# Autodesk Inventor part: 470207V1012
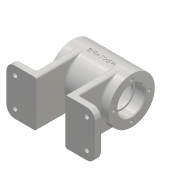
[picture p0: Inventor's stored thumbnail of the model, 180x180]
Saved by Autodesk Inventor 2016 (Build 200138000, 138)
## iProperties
Created: 2017-02
Part Number: 470207V1012
Material: 알루미늄 6061
Document SubType Name: Modeling
Designer: H
Density: 2.7 g/cm^3
Appearance: 알루미늄 - 평지
Mass: 354.768 g
Surface Area: 422.772 cm^2
Volume: 131.396 cm^3
Author: H
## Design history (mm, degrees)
sketch "스케치1"
  geometry: L1 (-35, 27)-(35, 27); L2 (35, 27)-(35, 0); L3 (35, 0)-(-35, 0); L4 (-35, 0)-(-35, 27); L5 (-70.456, 0)-(124.766, 0); 1 further point
  constraints: 10 end point, 2 horizontal, 2 parallel, 1 collinear, 1 perpendicular, 1 point on line
  dimensions: "d0" = 70 distance of L1.start L1.end; "d1" = 35 distance from line of L4 point (0, 0); "d2" = 27 distance of L1.end L2.end
revolve "회전1" sketch "스케치1" stored, may be unused: angle "d3" = 90 deg
sketch "스케치2"
  geometry: L1 (17, -52)-(52, -52); L2 (52, -52)-(52, -60); L3 (52, -60)-(17, -60); L4 (17, -60)-(17, -52); 1 further point
  constraints: 8 end point, 2 parallel, 1 horizontal, 1 perpendicular
  dimensions: "d4" = 35 distance of L2.end L3.end; "d5" = 8 distance of L1.end L2.end; "d6" = 17 distance from line of point (0, 0) L4; "d7" = 60 distance from line of L3 point (0, 0)
extrude "돌출1" join sketch "스케치2" stored distance "d8" = 54; taper "d9" = 0 deg
sketch "스케치3"
  geometry: L1 (17, 0)-(25, 0); L2 (25, 0)-(25, -60); L3 (25, -60)-(17, -60); L4 (17, -60)-(17, 0); L5 (17, -60)-(17, -52) reference; L6 (52, -60)-(17, -60) reference; 1 further point
  constraints: 8 end point, 2 collinear, 2 parallel, 1 horizontal, 1 perpendicular, 1 point on line
  dimensions: "d10" = 8 distance of L1.start L1.end
extrude "돌출2" join sketch "스케치3" stored distance "d12" = 54; taper "d13" = 0 deg
sketch "스케치4"
  geometry: L1 (-10, 44.214)-(-10, -7.125); L2 (-35, -27)-(-35, 27) reference; L3 (-15, 32)-(-10, 32); L4 (-10, 32)-(-10, 12); L5 (-10, 12)-(-15, 12); L6 (-15, 12)-(-15, 32); L7 (-35, 27)-(35, 27) reference; 1 further point
  constraints: 10 end point, 2 parallel, 1 collinear, 1 horizontal, 1 perpendicular, 1 vertical
  dimensions: "d14" = 25 distance between parallel lines of L1 L2; "d15" = 5 distance between parallel lines of L7 L3; "d16" = 5 distance of L3.start L3.end; "d17" = 20 distance of L5.end L3.start
revolve "회전2" sketch "스케치4" stored, may be unused: angle "d18" = 90 deg
sketch "스케치5"
  geometry: L1 (0, 0)-(-34.683, -22.523); L2 (0, 0)-(-46.212, 0); L3 (-8.387, -5.446)-(-25.16, -16.339); L4 (-25.16, -16.339)-(-21.892, -21.371); L5 (-21.892, -21.371)-(-5.119, -10.478); L6 (-5.119, -10.478)-(-8.387, -5.446); C1 r 27 at (0, 0) reference; 1 further point
  constraints: 12 end point, 2 parallel, 2 point on line, 1 horizontal, 1 perpendicular
  dimensions: "d19" = 33 deg angle of L2 L1; "d20" = 12 diameter of L5 L1; "d21" = 30 distance from line of L4 point (0, 0); "d22" = 20 distance between parallel lines of L4 L6
revolve "회전3" sketch "스케치5" stored, may be unused: angle "d23" = 90 deg
sketch "스케치6"
  geometry: C1 r 27 at (0, 0) reference; C2 r 16 at (0, 0); 1 further point
  constraints: 1 centre point, 1 coincident
  dimensions: "d24" = 32 diameter of C2
extrude "돌출3" cut sketch "스케치6" distance "d25" = 12; taper "d26" = 0 deg
sketch "스케치7"
  geometry: C1 r 14 at (0, 0); 1 further point
  constraints: 1 centre point, 1 coincident
  dimensions: "d27" = 28 diameter of C1
extrude "돌출4" cut sketch "스케치7" distance "d28" = 3; taper "d29" = 0 deg
sketch "스케치8"
  geometry: C1 r 22 at (0, 0); 1 further point
  constraints: 1 centre point, 1 coincident
  dimensions: "d30" = 44 diameter of C1
extrude "돌출5" cut sketch "스케치8" distance "d31" = 40; taper "d32" = 0 deg
sketch "스케치9"
  geometry: C1 r 5 at (0, 0) reference; 2 further points
  constraints: 1 coincident
hole "구멍1" sketch "스케치9" at (0, 0) diameter "d33" = 5.188; stored, may be unused: countersink angle "d37" = 90 deg, drill point angle "d39" = 118 deg; dims "d34" = 12, "d35" = 4, "d36" = 2, "d38" = 16
sketch "스케치10"
  geometry: C1 r 6 at (0, 0) reference; 2 further points
  constraints: 1 coincident
hole "구멍2" sketch "스케치10" at (0, 0) diameter "d40" = 5.188; stored, may be unused: countersink angle "d44" = 90 deg, drill point angle "d46" = 118 deg; dims "d41" = 12, "d42" = 4, "d43" = 2, "d45" = 16
sketch "스케치11"
  geometry: C1 r 27 at (0, 0) reference; 2 further points
  constraints: 1 vertical alignment
  dimensions: "d47" = 21 distance of point (0, 0) point (0, 21)
hole "구멍3" sketch "스케치11" at (0, 21) diameter "d48" = 3.242; stored, may be unused: countersink angle "d52" = 90 deg, drill point angle "d54" = 118 deg; dims "d49" = 8, "d50" = 4, "d51" = 2, "d53" = 10
fillet "모깎기1" dims "d58" = 10
sketch "스케치12"
  geometry: A1 r 10 centre (17, 10) between (17, 0) and (27, 10) reference; 2 further points
  constraints: 1 coincident
hole "구멍4" sketch "스케치12" at (17, 10) diameter "d59" = 5; stored, may be unused: countersink angle "d63" = 90 deg, drill point angle "d65" = 118 deg; dims "d60" = 8, "d61" = 4, "d62" = 2, "d64" = 10
fillet "모깎기2" dims "d75" = 0.3
fillet "모깎기3" dims "d76" = 2
fillet "모깎기4" dims "d77" = 2
fillet "모깎기5" dims "d78" = 2
fillet "모깎기6" dims "d79" = 2
chamfer "모따기1" distance "d80" = 1; stored, may be unused: second distance "d81" = 2, angle "d82" = 45 deg
chamfer "모따기2" distance "d83" = 1; stored, may be unused: second distance "d84" = 2, angle "d85" = 45 deg
fillet "모깎기7" dims "d86" = 2
fillet "모깎기8" dims "d87" = 3
node "작업 평면1"
sketch "스케치14"
  geometry: L1 (-35, 27)-(35, 27) reference; L2 (-35, -27)-(-35, 27) reference; 2 further points
  constraints: 1 other
  dimensions: "d89" = 27 distance from line of point (0, 0) L1; "d90" = 35 distance from line of L2 point (0, 0)
feature "엠보싱1" sketch "스케치14" dims "d91" = 0.5, "d92" = 0
sketch "스케치15" dims "d94" = 9
  geometry: L1 (12.402, 3.5)-(9.804, 8); L2 (9.804, 8)-(12.402, 12.5); L3 (12.402, 12.5)-(17.598, 12.5); L4 (17.598, 12.5)-(20.196, 8); L5 (20.196, 8)-(17.598, 3.5); L6 (17.598, 3.5)-(12.402, 3.5); C1 r 2.5 at (15, 8) reference; 4 further points
  constraints: 12 end point, 2 coincident, 1 midpoint, 1 vertical alignment, 15 other
extrude "돌출7" cut sketch "스케치15" distance "d95" = 3; taper "d96" = 0 deg
node "솔리드1"
mirror "대칭1"
mirror "대칭2"
pattern_circular "원형 패턴1" dims angle "d56" = 360 deg
mirror "대칭3"
pattern_linear "직사각형 패턴1" dims "d71" = 84, "d74" = 34
pattern_linear "직사각형 패턴2" dims "d99" = 34, "d102" = 84
other parameters: "d88" = 52.5
